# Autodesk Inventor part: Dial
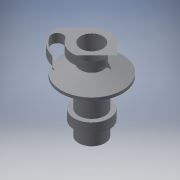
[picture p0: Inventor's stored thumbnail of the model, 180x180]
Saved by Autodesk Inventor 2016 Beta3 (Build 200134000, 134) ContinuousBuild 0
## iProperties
Shininess: 64.0
Length Units: 11272
Angle Units: 11279
Time Units: 11290
Mass Units: 11286
Length Display Precision: 3
Angle Display Precision: 2
Compacted: True
Created: 2001-11
Part Number: Dial
Document SubType Name: Modeling
Designer: Autodesk, Inc.
Mass: 1.0296 g
Surface Area: 19.0281 cm^2
Volume: 1.0296 cm^3
Density: 1 g/cm^3
Material: Generic
Appearance: Grey (Light)
Density: 0.0
Volumn: 0.0
Area: 0.0
PropertySet Name: Model Information
Control State: 0
Master: False
Checked Out: False
Author: Autodesk, Inc.
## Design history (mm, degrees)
sketch "Sketch1"
  geometry: L1 (120.263, 98.09)-(121.533, 98.09); L2 (121.533, 100.63)-(121.533, 98.09); L3 (121.533, 100.63)-(125.343, 100.63); L4 (125.343, 101.458)-(125.343, 100.63); L5 (119.755, 103.715)-(125.343, 101.458); L6 (119.755, 106.472)-(119.755, 103.715); L7 (119.755, 106.472)-(125.851, 106.472); L8 (125.851, 106.472)-(125.851, 109.012); L9 (116.453, 109.012)-(125.851, 109.012); L10 (116.453, 109.012)-(116.453, 86.66); L11 (116.453, 86.66)-(117.215, 86.66); L12 (117.215, 86.66)-(117.215, 85.644); L13 (117.215, 85.644)-(120.263, 85.644); L14 (120.263, 89.708)-(120.263, 85.644); L15 (120.263, 89.708)-(121.533, 89.708); L16 (121.533, 92.502)-(121.533, 89.708); L17 (120.263, 92.502)-(121.533, 92.502); L18 (120.263, 98.09)-(120.263, 92.502); L19 (116.453, 109.012)-(116.453, 86.66)
  constraints: 38 end point, 9 vertical, 8 horizontal, 2 collinear, 1 other
  dimensions: "d1" = 9.398 distance of L9.start L8.end; "d3" = 22.352 distance of L9.start L10.end; "d5" = 2.54 distance of L7.end L8.end; "d11" = 10.922 vertical distance of L9.start L1.end; "d13" = 8.382 vertical distance of L9.start L3.end; "d15" = 16.51 vertical distance of L16.start L8.end; "d17" = 19.304 vertical distance of L14.start L8.end; "d19" = 1.016 distance of L11.end L12.end; "d23" = 8.89 horizontal distance of L10.end L3.end; "d25" = 0.762 distance of L10.end L11.end; "d27" = 3.048 distance of L12.end L13.end; "d51" = 6.604 diameter of L6 L10
revolve "RevolutionFull1" sketch "Sketch1" stored, may be unused: angle "d28" = 360 deg
sketch "Sketch2"
  geometry: C1 r 3.302 at (0, 0) reference; A1 r 5.588 centre (0, 0) between (-4.761, -2.925) and (5.042, -2.408); A2 r 1.651 centre (6.532, -3.12) between (7.607, -1.867) and (5.042, -2.408); A3 r 1.651 centre (6.532, -3.12) between (8.022, -3.832) and (7.607, -1.867); A4 r 8.89 centre (0, 0) between (-7.575, -4.654) and (8.022, -3.832); A5 r 1.651 centre (-6.168, -3.79) between (-7.335, -2.622) and (-7.575, -4.654); A6 r 1.651 centre (-6.168, -3.79) between (-4.761, -2.925) and (-7.335, -2.622)
  constraints: 12 point on circle, 6 centre point, 5 tangent, 4 concentric
  dimensions: "d34" = 12.7 horizontal distance of A6.centre A3.centre; "d36" = 5.588 radius of A1; "d38" = 8.89 radius of A4
extrude "ExtrusionToFace1" cut sketch "Sketch2" stored distance "d39" = 3.302; taper "d40" = 0 deg
sketch "Sketch3"
  geometry: L1 (25.051, 17.256)-(-16.734, 17.256); L2 (25.051, -5.225)-(25.051, 17.256); L3 (25.051, -5.225)-(10.165, -5.225); L4 (3.682, 3.682)-(9.59, -2.226); L5 (-3.682, 3.682)-(-9.632, -2.268); L6 (-16.734, -6.364)-(-10.09, -5.233); L7 (-16.734, 17.256)-(-16.734, -6.364); C1 r 9.398 at (0, 0) reference; A1 r 2.721 centre (7.666, -4.15) between (10.165, -5.225) and (9.59, -2.226); A2 r 5.207 centre (0, 0) between (3.682, 3.682) and (-3.682, 3.682); A3 r 2.54 centre (-7.836, -4.064) between (-9.632, -2.268) and (-10.09, -5.233)
  constraints: 14 end point, 6 point on circle, 4 tangent, 3 centre point, 2 horizontal, 2 vertical, 1 concentric
extrude "ExtrusionBlind1" cut sketch "Sketch3" distance "d41" = 2.54; taper "d42" = 0 deg
sketch "Sketch4"
  geometry: L1 (-1.536, -9.906)-(0.457, -9.906); L2 (0.457, -9.906)-(0.734, -9.369); L3 (-1.536, -9.906)-(-2.352, -9.099); A1 r 9.398 centre (0, 0) between (-9.214, -1.85) and (9.214, -1.85) reference
  constraints: 6 end point, 2 point on circle, 1 horizontal, 1 other
  dimensions: "d44" = 9.906 dimension on L1.start
extrude "ExtrusionToPlane1" join sketch "Sketch4" stored distance "d45" = 3.302; taper "d46" = 0 deg
extrude "ExtrusionThru1" cut stored distance "d49" = 3.302; taper "d50" = 0 deg
  node "Sketch5" dims "d48" = 6.35
fillet "Fillet1" dims "d52" = 2.54
body "Solid1"
other parameters: "d0" = 9.398 (derived), "d2" = 22.352 (derived), "d4" = 2.54 (derived), "d6" = 5.08 (derived), "d8" = 6.604 (derived), "d10" = 10.922 (derived), "d12" = 8.382 (derived), "d14" = 16.51 (derived), "d16" = 19.304 (derived), "d18" = 1.016 (derived), "d20" = 158 deg (derived), "d22" = 8.89 (derived), "d24" = 0.762 (derived), "d26" = 3.048 (derived), "d29" = 0, "d30" = 0, "d31" = 0, "d32" = 0, "d33" = 12.7 (derived), "d35" = 5.588 (derived), "d37" = 8.89 (derived), "d43" = 9.906 (derived), "d47" = 6.35 (derived)
